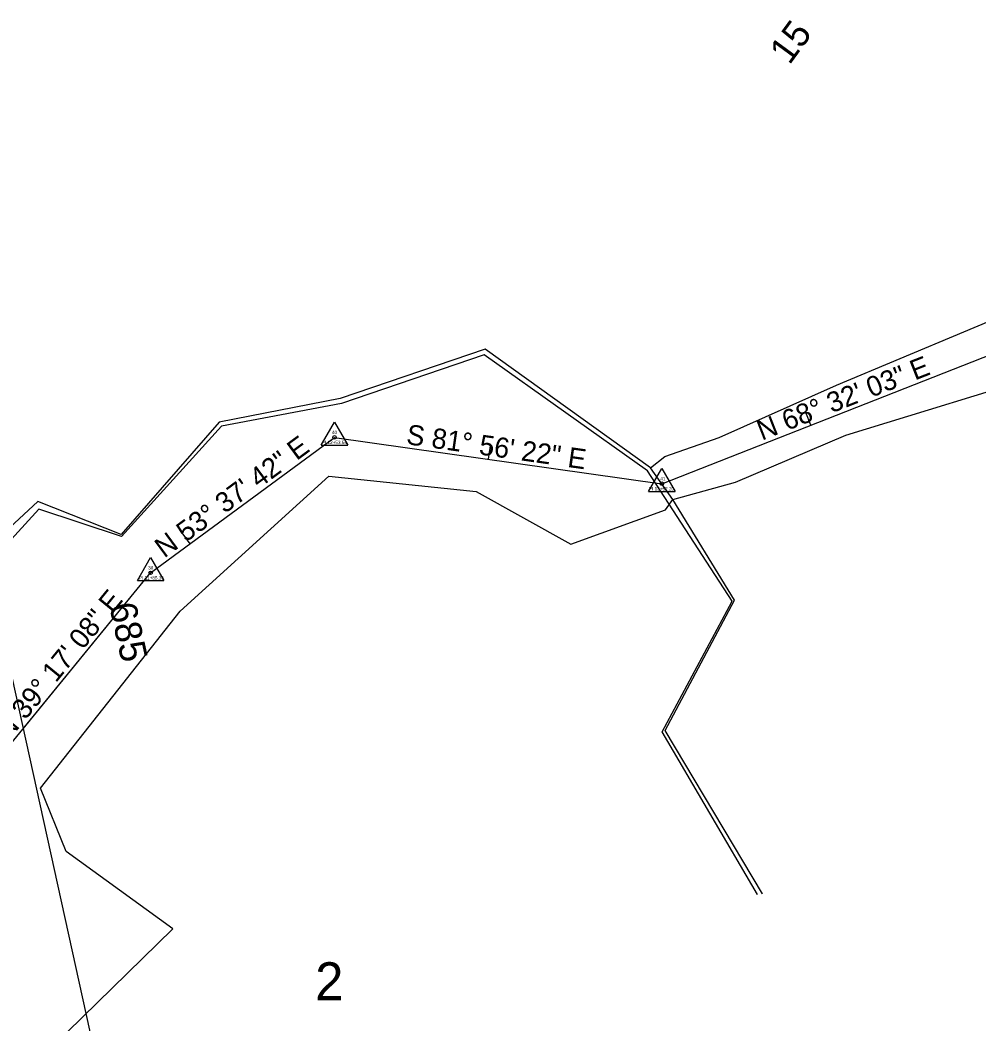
# Model space of a CAD drawing. Extents: x 2519952 to 2531965, y 848341 to 887632.
# Drawn here: x 2525674.8 to 2525961.1, y 850919.3 to 851219 of the extents above; entities that cross this region are included whole.
import ezdxf

# ---------------------------------------------------------------- set-up
doc = ezdxf.new("R2010")
doc.units = 0
for name, color, linetype in [('RD_EX_DV_Prop', 7, 'Continuous'), ('RD_EX_DV_TX_Prop', 7, 'Continuous'), ('RD_EX_H2O', 7, 'Continuous'), ('RD_EX_Misc', 7, 'Continuous'), ('RD_EX_RW', 7, 'Continuous'), ('RD_HC_Cl', 7, 'Continuous'), ('RD_HC_Data', 7, 'Continuous'), ('RD_HC_Data_Tic', 7, 'Continuous'), ('RD_HC_TX_Sta50', 7, 'Continuous'), ('RD_HC_txCode', 7, 'Continuous'), ('RD_SMD_Locator', 7, 'Continuous')]:
    doc.layers.add(name, color=color, linetype=linetype)

msp = doc.modelspace()

# ---------------------------------------------------------------- linework, layer by layer
at = {"layer": 'RD_EX_DV_Prop'}
for p, q in [((2525866.4, 851080.55), (2525979.55, 851125.04)), ((2525713.82, 851053.95), (2525768.72, 851094.38)), ((2525768.72, 851094.38), (2525866.4, 851080.55)), ((2525660.31, 851077.44), (2525724.82, 850784.46)), ((2525675.73, 851007.39), (2525713.82, 851053.95))]:
    msp.add_line(p, q, dxfattribs=at)
at = {"layer": 'RD_EX_H2O'}
for points in [[(2525863.08, 851085.28), (2525867.27, 851088.66), (2525883.49, 851094.37), (2525918.53, 851109.97), (2525975.54, 851133.87), (2526019.55, 851198.39)], [(2525895.01, 850957.87), (2525866.53, 851006.5), (2525887.38, 851045.44), (2525862.11, 851084.35), (2525813.41, 851119.01), (2525770.76, 851104.54), (2525734.99, 851097.73), (2525705.14, 851064.81), (2525680.47, 851072.96), (2525660.82, 851051.52), (2525657.08, 850999.33)], [(2525675.39, 850903.55), (2525720.41, 850947.65), (2525688.59, 850970.76), (2525680.97, 850989.65), (2525722.67, 851042.46), (2525767.05, 851082.8), (2525811.01, 851078.18), (2525839.21, 851062.49), (2525867.54, 851072.8), (2525869.68, 851075.88), (2525888.39, 851081), (2525921.38, 851095.03), (2525984.38, 851114.39)]]:
    msp.add_lwpolyline(points, dxfattribs=at)
at = {"layer": 'RD_EX_Misc'}
msp.add_lwpolyline([(2525896.46, 850958.07), (2525867.46, 851006.86), (2525888.1, 851045.78), (2525869.68, 851075.88), (2525863.08, 851085.28), (2525813.69, 851120.69), (2525770.39, 851105.99), (2525734.29, 851098.96), (2525705.02, 851065.38), (2525680.11, 851075.22), (2525657.81, 851054.65), (2525651.54, 851001.99)], dxfattribs=at)
at = {"layer": 'RD_EX_RW'}
msp.add_line((2525660.31, 851077.44), (2525724.82, 850784.46), dxfattribs=at)
at = {"layer": 'RD_HC_Cl'}
for p, q in [((2525866.4, 851080.55), (2525979.55, 851125.04)), ((2525713.82, 851053.95), (2525768.72, 851094.38)), ((2525768.72, 851094.38), (2525866.4, 851080.55)), ((2525666.26, 850995.82), (2525713.82, 851053.95))]:
    msp.add_line(p, q, dxfattribs=at)
at = {"layer": 'RD_HC_Data'}
for p, q in [((2525764.75, 851092.09), (2525768.72, 851098.97)), ((2525768.72, 851098.97), (2525772.69, 851092.09)), ((2525764.75, 851092.09), (2525772.69, 851092.09)), ((2525862.43, 851078.26), (2525866.4, 851085.14)), ((2525866.4, 851085.14), (2525870.37, 851078.26)), ((2525862.43, 851078.26), (2525870.37, 851078.26)), ((2525709.85, 851051.66), (2525713.82, 851058.54)), ((2525713.82, 851058.54), (2525717.79, 851051.66)), ((2525709.85, 851051.66), (2525717.79, 851051.66))]:
    msp.add_line(p, q, dxfattribs=at)
for centre in [(2525768.72, 851094.38), (2525866.4, 851080.55), (2525713.82, 851053.95)]:
    msp.add_circle(centre, 0.529, dxfattribs=at)
at = {"layer": 'RD_HC_Data_Tic'}
for p, q in [((2525910.88, 851098.04), (2525909.42, 851101.76)), ((2525814.71, 851087.87), (2525815.27, 851091.83)), ((2525725.6, 851062.63), (2525723.23, 851065.85))]:
    msp.add_line(p, q, dxfattribs=at)
at = {"layer": 'RD_SMD_Locator'}
for centre in [(2525813.41, 851119.01), (2525813.69, 851120.69), (2525918.53, 851109.97), (2525770.39, 851105.99), (2525770.76, 851104.54), (2525734.29, 851098.96), (2525734.99, 851097.73), (2525921.38, 851095.03), (2525768.72, 851094.38), (2525883.49, 851094.37), (2525867.27, 851088.66), (2525767.05, 851082.8), (2525862.11, 851084.35), (2525863.08, 851085.28), (2525863.08, 851085.28), (2525866.4, 851080.55), (2525888.39, 851081), (2525811.01, 851078.18), (2525680.11, 851075.22), (2525869.68, 851075.88), (2525869.68, 851075.88), (2525680.47, 851072.96), (2525867.54, 851072.8), (2525705.02, 851065.38), (2525705.14, 851064.81), (2525839.21, 851062.49), (2525713.82, 851053.95), (2525887.38, 851045.44), (2525888.1, 851045.78), (2525722.67, 851042.46), (2525866.53, 851006.5), (2525867.46, 851006.86), (2525680.97, 850989.65), (2525688.59, 850970.76), (2525895.01, 850957.87), (2525896.46, 850958.07), (2525720.41, 850947.65)]:
    msp.add_circle(centre, 0.001, dxfattribs=at)

# ---------------------------------------------------------------- texts
at = {"layer": 'RD_EX_DV_TX_Prop'}
msp.add_text('2', height=11.32, dxfattribs=at).set_placement((2525762.94, 850926.35))
at = {"layer": 'RD_HC_Data'}
for s, rotation, p in [('N 68%%d 32\' 03" E', 21.4658, (2525896.28, 851093.37)), ('S 81%%d 56\' 22" E', 351.9395, (2525789.91, 851092.39)), ('N 53%%d 37\' 42" E', 36.3717, (2525717.89, 851058.19)), ('N 39%%d 17\' 08" E', 50.7144, (2525671.35, 851003.62))]:
    msp.add_text(s, height=6, rotation=rotation, dxfattribs=at).set_placement(p)
at = {"layer": 'RD_HC_TX_Sta50'}
for s, rotation, p in [('15', 53.787, (2525904.5, 851205.35)), ('685', 282.4185, (2525701.42, 851044.2))]:
    msp.add_text(s, height=8, rotation=rotation, dxfattribs=at).set_placement(p)
at = {"layer": 'RD_HC_txCode'}
for s, p in [('40', (2525767.95, 851095.38)), ('PI 12+53.54', (2525764.94, 851092.38)), ('41', (2525865.95, 851081.55)), ('PI 13+52.20', (2525862.58, 851078.55)), ('39', (2525713.09, 851054.95)), ('PI 11+85.36', (2525710.3, 851051.95))]:
    msp.add_text(s, height=1, dxfattribs=at).set_placement(p)

doc.saveas('drawing.dxf')
